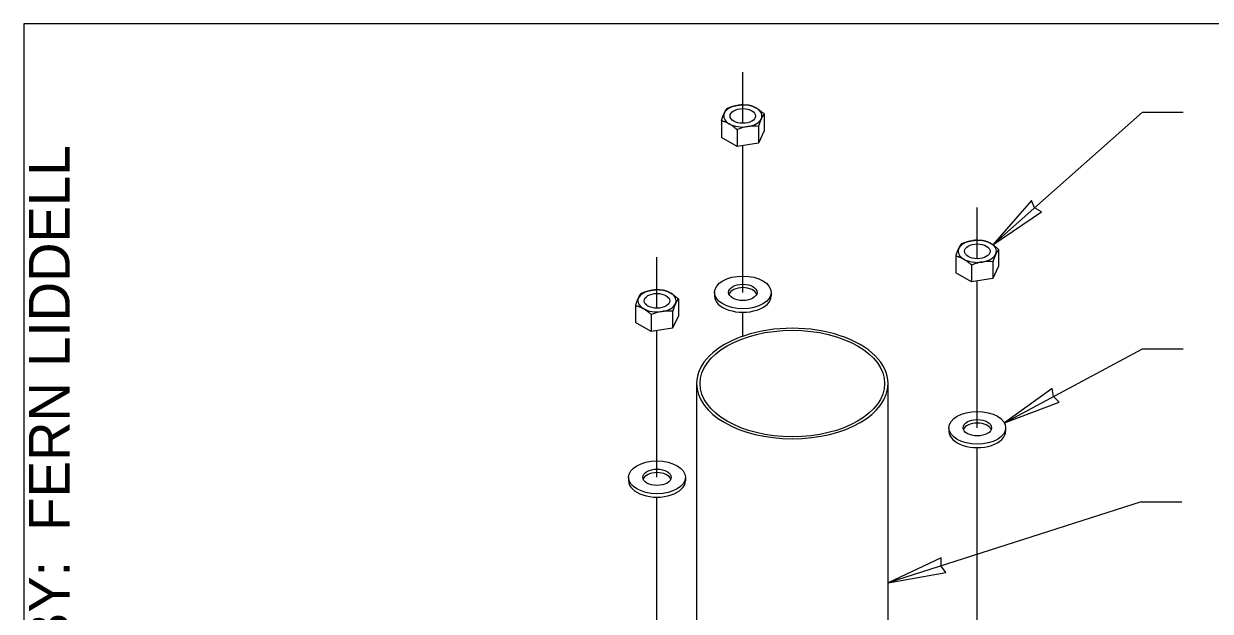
# Model space of a CAD drawing. Extents: x 99862 to 104211, y 98939 to 102076.
# Drawn here: x 99862 to 100326.8, y 101845.3 to 102075.5 of the extents above; entities that cross this region are included whole.
import ezdxf

# ---------------------------------------------------------------- set-up
doc = ezdxf.new("R2010")
doc.units = 0
for name, color, linetype in [('Level 1', 7, 'Continuous'), ('Level 15', 7, 'Continuous'), ('Level 6', 7, 'Continuous'), ('Level 62', 7, 'Continuous'), ('Level 8', 7, 'Continuous'), ('Level 9', 7, 'Continuous')]:
    doc.layers.add(name, color=color, linetype=linetype)

msp = doc.modelspace()

# ---------------------------------------------------------------- linework, layer by layer
at = {"layer": 'Level 1'}
msp.add_lwpolyline([(99862, 99999.5), (103151, 99999.5), (103151, 102075.5), (99862, 102075.5)], close=True, dxfattribs=at)
at = {"layer": 'Level 15'}
for p, q in [((100241.7, 101988.87), (100300.21, 102040.85)), ((100300.21, 102040.85), (100316.21, 102040.85)), ((100246.17, 101919.11), (100300.21, 101948.13)), ((100300.21, 101948.13), (100316.21, 101948.13)), ((100299.72, 101888.15), (100200.61, 101856.4)), ((100299.72, 101888.15), (100315.72, 101888.15))]:
    msp.add_line(p, q, dxfattribs=at)
for points in [[(100241.7, 101988.87), (100260.75, 102001.8), (100257.98, 102003.33), (100256.79, 102006.26)], [(100246.17, 101919.11), (100267.69, 101927.28), (100265.35, 101929.41), (100264.87, 101932.54)], [(100200.61, 101856.4), (100223.26, 101860.52), (100221.34, 101863.04), (100221.44, 101866.21)]]:
    msp.add_lwpolyline(points, close=True, dxfattribs=at)
at = {"layer": 'Level 6'}
for p, q in [((100143.7, 102036.49), (100143.7, 102056.49)), ((100143.7, 101970.25), (100143.7, 102027.75)), ((100235.55, 101983.45), (100235.55, 102003.45)), ((100110.07, 101964.04), (100110.07, 101984.04)), ((100235.55, 101917.21), (100235.55, 101974.71)), ((100143.7, 101953.07), (100143.7, 101962.47)), ((100110.08, 101897.8), (100110.08, 101955.3)), ((100235.55, 101749.22), (100235.55, 101909.44)), ((100110.07, 101729.81), (100110.07, 101890.03))]:
    msp.add_line(p, q, dxfattribs=at)
at = {"layer": 'Level 8'}
for p, q in [((100125.61, 101934.54), (100125.61, 101815.81)), ((100200.61, 101827.41), (100200.61, 101934.54))]:
    msp.add_line(p, q, dxfattribs=at)
for start_param, end_param in [(3.141593, 6.283199), (0.000014, 3.141593)]:
    msp.add_ellipse((100163.11, 101934.54), major_axis=(-37.5, 0), ratio=0.57735, start_param=start_param, end_param=end_param, dxfattribs=at)
msp.add_ellipse((100163.11, 101934.54), major_axis=(-36.15, 0), ratio=0.57735, dxfattribs=at)
at = {"layer": 'Level 9'}
for p, q in [((100141.56, 102043.53), (100141.95, 102043.59)), ((100148.87, 102042.51), (100149.13, 102042.36)), ((100135.33, 102037.53), (100135.33, 102030.94)), ((100136.41, 102040.41), (100136.49, 102040.58)), ((100150.97, 102038.31), (100150.91, 102038.2)), ((100152.06, 102040.12), (100152.06, 102033.52)), ((100141.46, 102034), (100141.46, 102027.4)), ((100149.82, 102035.29), (100149.82, 102028.69)), ((100152.06, 102033.52), (100149.82, 102028.69)), ((100141.46, 102027.4), (100135.33, 102030.94)), ((100149.82, 102028.69), (100141.46, 102027.4)), ((100228.27, 101987.37), (100228.35, 101987.55)), ((100233.41, 101990.49), (100233.81, 101990.55)), ((100240.72, 101989.48), (100240.98, 101989.33)), ((100243.92, 101987.09), (100243.92, 101980.49)), ((100227.19, 101984.5), (100227.19, 101977.9)), ((100241.68, 101982.26), (100241.68, 101975.66)), ((100242.82, 101985.28), (100242.77, 101985.17)), ((100233.31, 101974.37), (100227.19, 101977.9)), ((100233.31, 101980.96), (100233.31, 101974.37)), ((100243.92, 101980.49), (100241.68, 101975.66)), ((100241.68, 101975.66), (100233.31, 101974.37)), ((100102.79, 101967.96), (100102.87, 101968.14)), ((100107.94, 101971.08), (100108.33, 101971.14)), ((100115.25, 101970.07), (100115.51, 101969.92)), ((100132.59, 101970.25), (100132.59, 101968.89)), ((100154.81, 101970.25), (100154.81, 101968.89)), ((100101.71, 101965.09), (100101.71, 101958.49)), ((100117.34, 101965.86), (100117.29, 101965.75)), ((100118.44, 101967.68), (100118.44, 101961.08)), ((100107.83, 101961.55), (100107.83, 101954.96)), ((100116.2, 101962.85), (100116.2, 101956.25)), ((100118.44, 101961.08), (100116.2, 101956.25)), ((100107.83, 101954.96), (100101.71, 101958.49)), ((100116.2, 101956.25), (100107.83, 101954.96)), ((100224.44, 101917.21), (100224.44, 101915.85)), ((100246.66, 101917.21), (100246.66, 101915.85)), ((100098.96, 101897.8), (100098.96, 101896.44)), ((100121.19, 101897.8), (100121.19, 101896.44))]:
    msp.add_line(p, q, dxfattribs=at)
for centre, major_axis, start_param, end_param in [((100143.7, 102039.37), (7.5, 0), 1.859837, 2.858903), ((100143.7, 102039.37), (7.5, 0), 0.810125, 1.805354), ((100143.7, 102039.37), (7.5, 0), 6.034615, 7.043856), ((100143.7, 102039.37), (7.5, 0), 2.900683, 3.926991), ((100143.7, 102039.37), (7.5, 0), 3.926991, 6.008202), ((100235.55, 101986.34), (7.5, 0), 2.900683, 3.926991), ((100235.55, 101986.34), (7.5, 0), 1.859837, 2.858903), ((100235.55, 101986.34), (7.5, 0), 0.810125, 1.805354), ((100235.55, 101986.34), (7.5, 0), 6.034615, 7.043856), ((100235.55, 101986.34), (7.5, 0), 3.926991, 6.008202), ((100110.07, 101966.93), (7.5, 0), 2.900683, 3.926991), ((100110.07, 101966.93), (7.5, 0), 1.859837, 2.858903), ((100110.07, 101966.93), (7.5, 0), 0.810125, 1.805354), ((100110.07, 101966.93), (7.5, 0), 6.034615, 7.043856), ((100143.7, 101968.89), (-11.11, 0), 0, 3.141593), ((100143.7, 101968.89), (-5.56, 0), 3.355069, 6.069709), ((100110.07, 101966.93), (7.5, 0), 3.926991, 6.008202), ((100235.55, 101915.85), (-5.56, 0), 3.355069, 6.069709), ((100235.55, 101915.85), (-11.11, 0), 0, 3.141593), ((100110.08, 101896.44), (-5.56, 0), 3.355069, 6.069709), ((100110.08, 101896.44), (-11.11, 0), 6.283185, 9.424778)]:
    msp.add_ellipse(centre, major_axis=major_axis, ratio=0.57735, start_param=start_param, end_param=end_param, dxfattribs=at)
for centre, major_axis in [((100143.7, 102039.37), (5, 0)), ((100235.55, 101986.34), (5, 0)), ((100143.7, 101970.25), (-11.11, 0)), ((100143.7, 101970.25), (-5.56, 0)), ((100110.07, 101966.93), (5, 0)), ((100235.55, 101917.21), (-11.11, 0)), ((100235.55, 101917.21), (-5.56, 0)), ((100110.08, 101897.8), (-11.11, 0)), ((100110.08, 101897.8), (-5.56, 0))]:
    msp.add_ellipse(centre, major_axis=major_axis, ratio=0.57735, dxfattribs=at)
for points, degree in [([(100136.49, 102040.58), (100136.86, 102041.36), (100137.22, 102041.92), (100137.57, 102042.36)], 2), ([(100137.57, 102042.36), (100138.88, 102042.88), (100140.2, 102043.3), (100141.56, 102043.53)], 2), ([(100141.95, 102043.59), (100143.31, 102043.78), (100144.64, 102043.77), (100145.94, 102043.66)], 2), ([(100145.94, 102043.66), (100146.89, 102043.42), (100147.88, 102043.07), (100148.87, 102042.51)], 2), ([(100149.13, 102042.36), (100149.63, 102042.06), (100150.13, 102041.72), (100151.11, 102040.96), (100151.59, 102040.55), (100152.06, 102040.12)], 3), ([(100135.33, 102037.53), (100135.69, 102038.62), (100136.05, 102039.6), (100136.41, 102040.41)], 2), ([(100135.33, 102037.53), (100136.33, 102037.29), (100137.36, 102036.91), (100138.39, 102036.31)], 2), ([(100150.91, 102038.2), (100150.54, 102037.39), (100150.18, 102036.39), (100149.82, 102035.29)], 2), ([(100152.06, 102040.12), (100151.7, 102039.68), (100151.34, 102039.1), (100150.97, 102038.31)], 2), ([(100138.39, 102036.31), (100138.91, 102036.01), (100139.44, 102035.66), (100140.46, 102034.88), (100140.96, 102034.45), (100141.46, 102034)], 3), ([(100149.82, 102035.29), (100148.45, 102035.41), (100147.07, 102035.41), (100144.22, 102034.97), (100142.82, 102034.54), (100141.46, 102034)], 3), ([(100227.19, 101984.5), (100227.54, 101985.58), (100227.9, 101986.57), (100228.27, 101987.37)], 2), ([(100228.35, 101987.55), (100228.72, 101988.33), (100229.08, 101988.89), (100229.43, 101989.33)], 2), ([(100229.43, 101989.33), (100230.73, 101989.85), (100232.06, 101990.26), (100233.41, 101990.49)], 2), ([(100233.81, 101990.55), (100235.17, 101990.75), (100236.49, 101990.74), (100237.79, 101990.62)], 2), ([(100237.79, 101990.62), (100238.75, 101990.39), (100239.73, 101990.03), (100240.72, 101989.48)], 2), ([(100240.98, 101989.33), (100241.48, 101989.03), (100241.98, 101988.69), (100242.96, 101987.93), (100243.44, 101987.52), (100243.92, 101987.09)], 3), ([(100243.92, 101987.09), (100243.56, 101986.64), (100243.19, 101986.07), (100242.82, 101985.28)], 2), ([(100227.19, 101984.5), (100228.18, 101984.26), (100229.21, 101983.88), (100230.25, 101983.28)], 2), ([(100230.25, 101983.28), (100230.77, 101982.98), (100231.29, 101982.62), (100232.31, 101981.84), (100232.82, 101981.42), (100233.31, 101980.96)], 3), ([(100241.68, 101982.26), (100240.31, 101982.38), (100238.92, 101982.38), (100236.08, 101981.94), (100234.68, 101981.51), (100233.31, 101980.96)], 3), ([(100242.77, 101985.17), (100242.4, 101984.35), (100242.03, 101983.35), (100241.68, 101982.26)], 2), ([(100101.71, 101965.09), (100102.06, 101966.17), (100102.42, 101967.16), (100102.79, 101967.96)], 2), ([(100102.87, 101968.14), (100103.24, 101968.92), (100103.6, 101969.48), (100103.95, 101969.92)], 2), ([(100103.95, 101969.92), (100105.26, 101970.44), (100106.58, 101970.85), (100107.94, 101971.08)], 2), ([(100108.33, 101971.14), (100109.69, 101971.33), (100111.01, 101971.33), (100112.32, 101971.21)], 2), ([(100112.32, 101971.21), (100113.27, 101970.98), (100114.26, 101970.62), (100115.25, 101970.07)], 2), ([(100115.51, 101969.92), (100116, 101969.62), (100116.51, 101969.27), (100117.48, 101968.52), (100117.96, 101968.11), (100118.44, 101967.68)], 3), ([(100101.71, 101965.09), (100102.71, 101964.85), (100103.74, 101964.47), (100104.77, 101963.87)], 2), ([(100104.77, 101963.87), (100105.29, 101963.57), (100105.81, 101963.21), (100106.84, 101962.43), (100107.34, 101962), (100107.83, 101961.55)], 3), ([(100117.29, 101965.75), (100116.92, 101964.94), (100116.56, 101963.94), (100116.2, 101962.85)], 2), ([(100118.44, 101967.68), (100118.08, 101967.23), (100117.72, 101966.66), (100117.34, 101965.86)], 2), ([(100116.2, 101962.85), (100114.83, 101962.97), (100113.45, 101962.97), (100110.6, 101962.53), (100109.2, 101962.1), (100107.83, 101961.55)], 3)]:
    msp.add_open_spline(points, degree=degree, dxfattribs=at)

# ---------------------------------------------------------------- texts
at = {"layer": 'Level 62'}
msp.add_text('DRAWN BY:  FERN LIDDELL', height=16, rotation=90, dxfattribs=at).set_placement((99880, 101743.72))

doc.saveas('drawing.dxf')
